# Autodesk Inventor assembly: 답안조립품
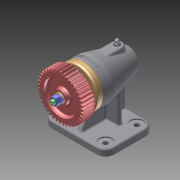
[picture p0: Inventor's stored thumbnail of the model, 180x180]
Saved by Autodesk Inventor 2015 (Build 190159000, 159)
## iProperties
Created: 2024-12
Part Number: 답안조립품
Document SubType Name: Assembly
Designer: 10401
Author: 10401
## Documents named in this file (15)
- C:\Users\10401\Desktop\741204V1009\답안조립품.iam
- C:\Users\10401\Desktop\741204V1009\그리스 니플 M6x0.75.ipt
- C:\Users\10401\Desktop\741204V1009\본체.ipt
- C:\Users\10401\Desktop\741204V1009\스퍼기어.ipt
- C:\Users\10401\Desktop\741204V1009\스프링 와셔 M8.ipt
- C:\Users\10401\Desktop\741204V1009\실링.ipt
- C:\Users\10401\Desktop\741204V1009\앵귤러 볼 베어링 7003A.ipt
- C:\Users\10401\Desktop\741204V1009\앵귤러 볼 제어링 7204A.ipt
- C:\Users\10401\Desktop\741204V1009\오일 실 20 32 8.ipt
- C:\Users\10401\Desktop\741204V1009\육각 너트 M8.ipt
- C:\Users\10401\Desktop\741204V1009\육각 소켓 머리 볼트 M4x10.ipt
- C:\Users\10401\Desktop\741204V1009\축.ipt
- C:\Users\10401\Desktop\741204V1009\커버.ipt
- C:\Users\10401\Desktop\741204V1009\평와셔 M8.ipt
- C:\Users\10401\Desktop\741204V1009\평행 키 4x4x14.ipt
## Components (1 placed, 1 different names)
1. 그리스 니플 M6x0.75:1
